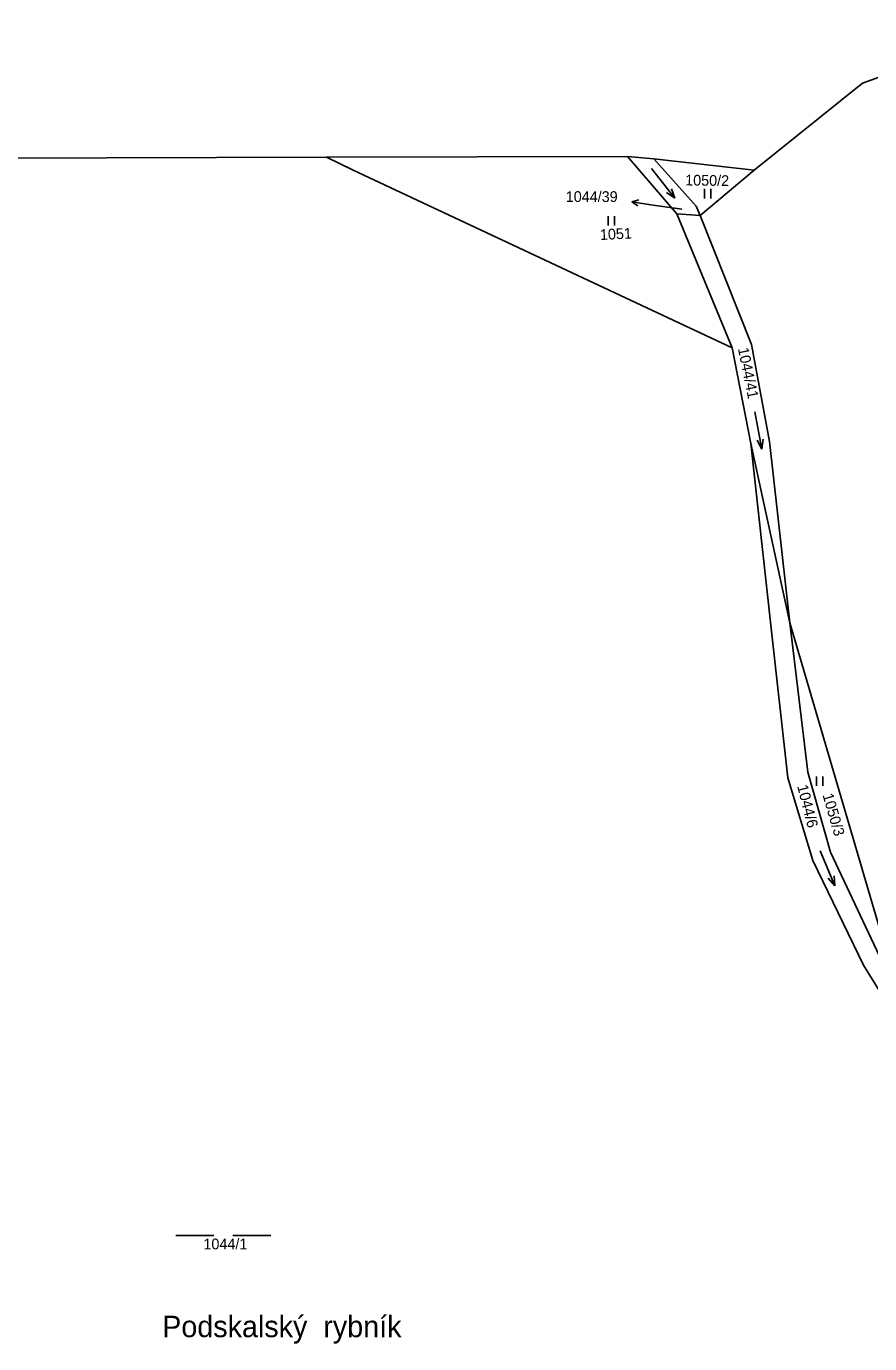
# Model space of a CAD drawing. Extents: x -795483 to -789093, y -1112258 to -1108741.
# Drawn here: x -792090.7 to -791957.1, y -1109292.9 to -1109084.2 of the extents above; entities that cross this region are included whole.
import ezdxf

# ---------------------------------------------------------------- set-up
doc = ezdxf.new("R2010")
doc.units = 0
for name, color, linetype in [('Komunikace', 7, 'Continuous'), ('Vrstva 1', 7, 'Continuous'), ('Vrstva 14', 7, 'Continuous'), ('Vrstva 16', 7, 'Continuous'), ('Vrstva 23', 7, 'Continuous'), ('Vrstva 4', 7, 'Continuous'), ('Vrstva 43', 7, 'Continuous')]:
    doc.layers.add(name, color=color, linetype=linetype)

msp = doc.modelspace()

# ---------------------------------------------------------------- linework, layer by layer
at = {"layer": 'Komunikace'}
msp.add_line((-791986.85, -1109113.15), (-791991.8, -1109112.42), dxfattribs=at)
at = {"layer": 'Vrstva 1'}
for p, q in [((-791995.5, -1109104.76), (-791987.65, -1109113.85)), ((-792039.05, -1109106.9), (-792043.19, -1109104.89)), ((-791984.58, -1109112.63), (-791991.31, -1109105.16)), ((-792032.17, -1109110.13), (-792039.05, -1109106.9)), ((-791983.99, -1109114.12), (-791975.44, -1109106.94)), ((-791978.91, -1109135.13), (-792032.17, -1109110.13)), ((-791983.99, -1109114.12), (-791984.58, -1109112.63)), ((-791987.65, -1109113.85), (-791978.91, -1109135.13)), ((-791987.65, -1109113.85), (-791983.99, -1109114.12)), ((-791975.85, -1109134.57), (-791983.99, -1109114.12)), ((-791975.97, -1109150.27), (-791978.91, -1109135.13)), ((-791972.99, -1109149.94), (-791975.85, -1109134.57)), ((-791972.77, -1109179.05), (-791975.97, -1109150.27)), ((-791975.97, -1109150.27), (-791969.78, -1109178.68)), ((-791969.78, -1109178.68), (-791972.99, -1109149.94)), ((-791970.06, -1109203.26), (-791972.77, -1109179.05)), ((-791966.89, -1109202.37), (-791969.78, -1109178.68)), ((-791969.78, -1109178.68), (-791953.08, -1109235.53)), ((-791963.33, -1109215), (-791966.89, -1109202.37)), ((-791966.14, -1109216.33), (-791970.06, -1109203.26)), ((-791955.64, -1109231.42), (-791963.33, -1109215)), ((-791958.1, -1109232.94), (-791966.14, -1109216.33)), ((-791948.24, -1109248.89), (-791958.1, -1109232.94))]:
    msp.add_line(p, q, dxfattribs=at)
at = {"layer": 'Vrstva 16'}
for p, q in [((-791994.77, -1109111.99), (-791993.71, -1109111.64)), ((-791991.8, -1109112.42), (-791994.77, -1109111.99)), ((-791994.77, -1109111.99), (-791993.85, -1109112.62))]:
    msp.add_line(p, q, dxfattribs=at)
at = {"layer": 'Vrstva 23'}
for p, q in [((-791991.67, -1109106.66), (-791987.97, -1109111.38)), ((-791987.97, -1109111.38), (-791989.29, -1109110.51)), ((-791987.97, -1109111.38), (-791988.5, -1109109.89)), ((-791983.29, -1109111.42), (-791983.29, -1109109.92)), ((-791982.29, -1109109.92), (-791982.29, -1109111.42)), ((-791998.53, -1109115.73), (-791998.53, -1109114.23)), ((-791997.53, -1109114.23), (-791997.53, -1109115.73)), ((-791975.32, -1109145.25), (-791974.18, -1109151.14)), ((-791974.18, -1109151.14), (-791974.95, -1109149.76)), ((-791974.18, -1109151.14), (-791973.97, -1109149.57)), ((-791965.52, -1109204.52), (-791965.52, -1109203.02)), ((-791964.52, -1109203.02), (-791964.52, -1109204.52)), ((-791964.94, -1109214.8), (-791962.66, -1109220.35)), ((-791962.66, -1109220.35), (-791963.69, -1109219.16)), ((-791962.66, -1109220.35), (-791962.77, -1109218.78)), ((-792067.01, -1109275.76), (-792061.01, -1109275.76)), ((-792058.01, -1109275.76), (-792052.01, -1109275.76))]:
    msp.add_line(p, q, dxfattribs=at)
at = {"layer": 'Vrstva 4'}
for p, q in [((-791958.25, -1109093.15), (-791933.35, -1109084.16)), ((-791958.25, -1109093.15), (-791975.44, -1109106.94)), ((-792043.19, -1109104.89), (-791995.5, -1109104.76)), ((-791995.5, -1109104.76), (-791991.31, -1109105.16)), ((-792102.6, -1109105.05), (-792043.19, -1109104.89)), ((-791975.44, -1109106.94), (-791991.31, -1109105.16))]:
    msp.add_line(p, q, dxfattribs=at)

# ---------------------------------------------------------------- texts
at = {"layer": 'Vrstva 14'}
for s, rotation, p in [('1050/2', 359.2361, (-791986.35, -1109109.37)), ('1051', 3.0069, (-791999.8, -1109118.03)), ('1044/41', 281.4825, (-791978, -1109135.22)), ('1044/6', 284.324, (-791968.62, -1109204.56)), ('1050/3', 286.1378, (-791964.6, -1109205.96))]:
    msp.add_text(s, height=1.7, rotation=rotation, dxfattribs=at).set_placement(p)
for s, height, p in [('1044/39', 0.1, (-791986.85, -1109113.15)), ('1044/1', 1.7, (-792062.66, -1109277.96))]:
    msp.add_text(s, height=height, dxfattribs=at).set_placement(p)
at = {"layer": 'Vrstva 16'}
msp.add_text('1044/39', height=1.7, dxfattribs=at).set_placement((-792005.26, -1109111.99))
at = {"layer": 'Vrstva 43'}
msp.add_text('Podskalský  rybník', height=3.4, dxfattribs=at).set_placement((-792069.19, -1109291.88))

doc.saveas('drawing.dxf')
